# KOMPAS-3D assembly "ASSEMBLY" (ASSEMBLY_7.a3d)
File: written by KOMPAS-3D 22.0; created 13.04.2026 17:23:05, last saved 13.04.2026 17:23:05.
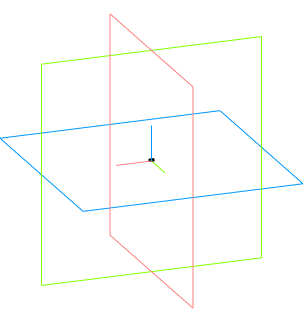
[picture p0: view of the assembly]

Document properties: Автор: Andrey; Полное имя файла: C:\Users\User1\Documents\ASSEMBLY_7.a3d

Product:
- Component [detail]: term1  | qty 1  | source file: term1_8.m3d
- Component [detail]: term2  | qty 1  | source file: term2_9.m3d
- Component [detail]: body  | qty 1  | source file: body_10.m3d
- Part/product: ASSEMBLY

Referenced files in C:\Users\User1\Documents\: term1_8.m3d, term2_9.m3d, body_10.m3d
